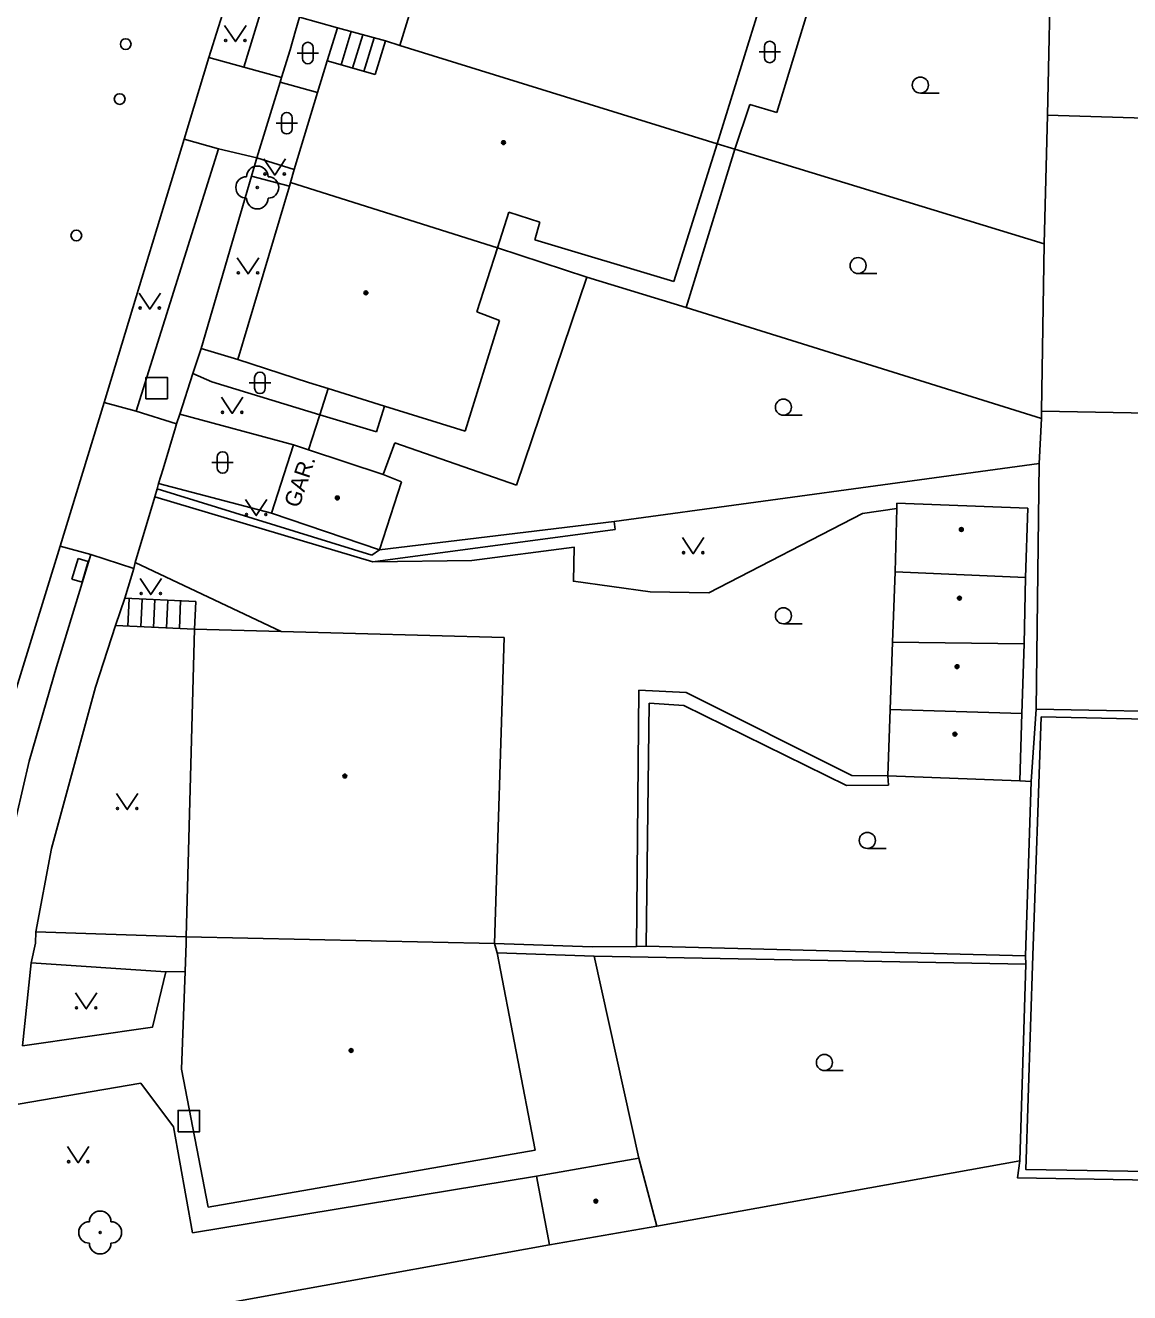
# Model space of a CAD drawing. Extents: x -600391 to -599491, y -1160176 to -1159402.
# Drawn here: x -599993.5 to -599942, y -1159653.5 to -1159594.4 of the extents above; entities that cross this region are included whole.
import ezdxf

# ---------------------------------------------------------------- set-up
doc = ezdxf.new("R2010")
doc.units = 0
for name, color, linetype in [('Level 10', 7, 'Continuous'), ('Level 11', 7, 'Continuous'), ('Level 22', 7, 'Continuous'), ('Level 26', 7, 'Continuous'), ('Level 28', 7, 'Continuous'), ('Level 36', 7, 'Continuous'), ('Level 39', 7, 'Continuous'), ('Level 41', 7, 'Continuous'), ('Level 5', 7, 'Continuous'), ('Level 51', 7, 'Continuous'), ('Level 52', 7, 'Continuous'), ('Level 6', 7, 'Continuous'), ('Level 7', 7, 'Continuous'), ('Level 8', 7, 'Continuous')]:
    doc.layers.add(name, color=color, linetype=linetype)

msp = doc.modelspace()

# ---------------------------------------------------------------- linework, layer by layer
at = {"layer": 'Level 10'}
for points in [[(-599984.03, -1159593.07), (-599984.92, -1159595.95)], [(-599984.92, -1159595.95), (-599986.07, -1159599.75)], [(-599986.07, -1159599.75), (-599988.15, -1159606.58), (-599989.8, -1159612.02)], [(-599989.8, -1159612.02), (-599991.85, -1159618.71)], [(-599991.85, -1159618.71), (-599998.93, -1159641.65)]]:
    msp.add_lwpolyline(points, dxfattribs=at)
at = {"layer": 'Level 11'}
for points in [[(-599982.43, -1159593.55), (-599983.3, -1159596.39)], [(-599979.42, -1159596.1), (-599978.93, -1159594.56)], [(-599978.77, -1159596.28), (-599978.29, -1159594.73)], [(-599978.24, -1159596.44), (-599977.75, -1159594.88)], [(-599977.71, -1159596.59), (-599977.22, -1159595.02)], [(-599983.3, -1159596.39), (-599984.92, -1159595.95)], [(-599983.3, -1159596.39), (-599981.54, -1159596.87)], [(-599982.69, -1159600.62), (-599981.61, -1159597.09)], [(-599986.07, -1159599.75), (-599984.47, -1159600.2)], [(-599984.47, -1159600.2), (-599988.31, -1159612.42)], [(-599984.47, -1159600.2), (-599982.69, -1159600.62)], [(-599982.69, -1159600.62), (-599982.94, -1159601.48)], [(-599980.95, -1159601.17), (-599982.69, -1159600.62)], [(-599983.58, -1159610.01), (-599985.29, -1159609.51)], [(-599985.68, -1159610.67), (-599984.79, -1159611.06), (-599979.75, -1159612.59)], [(-599979.75, -1159612.59), (-599979.37, -1159611.37)], [(-599988.31, -1159612.42), (-599989.8, -1159612.02)], [(-599976.75, -1159612.2), (-599977.11, -1159613.39)], [(-599988.31, -1159612.42), (-599986.43, -1159613.02)], [(-599980.98, -1159613.99), (-599986.28, -1159612.57)], [(-599980.29, -1159614.22), (-599979.77, -1159612.65)], [(-599979.77, -1159612.65), (-599979.75, -1159612.59)], [(-599979.75, -1159612.59), (-599977.11, -1159613.39)], [(-599982.01, -1159617.18), (-599987.27, -1159615.8)], [(-599991.85, -1159618.71), (-599990.42, -1159619.1)], [(-599990.42, -1159619.1), (-599992.02, -1159624.34), (-599993.3, -1159628.73), (-599994.19, -1159632.56), (-599994.89, -1159636.47), (-599995.74, -1159641.86)], [(-599991.31, -1159620.25), (-599991.02, -1159619.29)], [(-599991.02, -1159619.29), (-599990.55, -1159619.43)], [(-599990.55, -1159619.43), (-599990.83, -1159620.39)], [(-599990.42, -1159619.1), (-599988.42, -1159619.75)], [(-599988.36, -1159619.48), (-599981.56, -1159622.7)], [(-599990.83, -1159620.39), (-599991.31, -1159620.25)], [(-599988.84, -1159621.14), (-599985.54, -1159621.29)], [(-599988.7, -1159622.45), (-599988.64, -1159621.15)], [(-599988.1, -1159622.48), (-599988.04, -1159621.18)], [(-599987.44, -1159621.2), (-599987.5, -1159622.5)], [(-599986.9, -1159622.53), (-599986.84, -1159621.23)], [(-599986.24, -1159621.26), (-599986.3, -1159622.56)], [(-599985.6, -1159622.59), (-599985.54, -1159621.29)], [(-599985.6, -1159622.59), (-599989.28, -1159622.42)], [(-599993.2, -1159638.14), (-599986.93, -1159638.55)], [(-599986.93, -1159638.55), (-599987.55, -1159641.13), (-599993.61, -1159642)], [(-599986.93, -1159638.55), (-599986.03, -1159638.54)], [(-599988.1, -1159643.75), (-599993.81, -1159644.72)], [(-599986.58, -1159645.78), (-599988.1, -1159643.75)], [(-599985.69, -1159650.72), (-599986.58, -1159645.78)], [(-599969.66, -1159648.08), (-599985.69, -1159650.72)]]:
    msp.add_lwpolyline(points, dxfattribs=at)
at = {"layer": 'Level 22'}
for centre in [(-599982.67, -1159602), (-599989.99, -1159650.7)]:
    msp.add_circle(centre, 0.05, dxfattribs=at)
for centre, start, end in [((-599982.67, -1159601.5), 0, 180), ((-599983.17, -1159602), 90, 270), ((-599982.17, -1159602), 270, 90), ((-599982.67, -1159602.5), 180, 0), ((-599989.99, -1159650.2), 0, 180), ((-599990.49, -1159650.7), 90, 270), ((-599989.49, -1159650.7), 270, 90), ((-599989.99, -1159651.2), 180, 0)]:
    msp.add_arc(centre, 0.5, start, end, dxfattribs=at)
at = {"layer": 'Level 26'}
for points in [[(-599987.86, -1159611.85), (-599986.86, -1159611.85), (-599986.86, -1159610.85), (-599987.86, -1159610.85)], [(-599986.36, -1159646.01), (-599985.36, -1159646.01), (-599985.36, -1159645.01), (-599986.36, -1159645.01)]]:
    msp.add_lwpolyline(points, close=True, dxfattribs=at)
at = {"layer": 'Level 28'}
for centre in [(-599988.8, -1159595.32), (-599989.08, -1159597.88), (-599991.1, -1159604.24)]:
    msp.add_circle(centre, 0.25, dxfattribs=at)
at = {"layer": 'Level 36'}
for p, q in [((-599980.816, -1159595.736), (-599979.816, -1159595.736)), ((-599980.566, -1159595.486), (-599980.566, -1159595.986)), ((-599980.066, -1159595.486), (-599980.066, -1159595.986)), ((-599959.296, -1159595.686), (-599958.296, -1159595.686)), ((-599959.046, -1159595.436), (-599959.046, -1159595.936)), ((-599958.546, -1159595.436), (-599958.546, -1159595.936)), ((-599951.78, -1159597.605), (-599950.905, -1159597.605)), ((-599981.546, -1159598.756), (-599981.546, -1159599.256)), ((-599981.046, -1159598.756), (-599981.046, -1159599.256)), ((-599981.796, -1159599.006), (-599980.796, -1159599.006)), ((-599954.68, -1159606.015), (-599953.805, -1159606.015)), ((-599983.046, -1159611.106), (-599982.046, -1159611.106)), ((-599982.796, -1159610.856), (-599982.796, -1159611.356)), ((-599982.296, -1159610.856), (-599982.296, -1159611.356)), ((-599958.16, -1159612.615), (-599957.285, -1159612.615)), ((-599984.536, -1159614.566), (-599984.536, -1159615.066)), ((-599984.036, -1159614.566), (-599984.036, -1159615.066)), ((-599984.786, -1159614.816), (-599983.786, -1159614.816)), ((-599958.16, -1159622.335), (-599957.285, -1159622.335)), ((-599954.25, -1159632.805), (-599953.375, -1159632.805)), ((-599956.25, -1159643.155), (-599955.375, -1159643.155))]:
    msp.add_line(p, q, dxfattribs=at)
for points in [[(-599984.19, -1159594.45), (-599983.69, -1159595.2), (-599983.19, -1159594.45)], [(-599982.36, -1159600.67), (-599981.86, -1159601.42), (-599981.36, -1159600.67)], [(-599983.6, -1159605.28), (-599983.1, -1159606.03), (-599982.6, -1159605.28)], [(-599988.18, -1159606.92), (-599987.68, -1159607.67), (-599987.18, -1159606.92)], [(-599984.34, -1159611.78), (-599983.84, -1159612.53), (-599983.34, -1159611.78)], [(-599983.22, -1159616.54), (-599982.72, -1159617.29), (-599982.22, -1159616.54)], [(-599962.86, -1159618.32), (-599962.36, -1159619.07), (-599961.86, -1159618.32)], [(-599988.13, -1159620.22), (-599987.63, -1159620.97), (-599987.13, -1159620.22)], [(-599989.23, -1159630.24), (-599988.73, -1159630.99), (-599988.23, -1159630.24)], [(-599991.14, -1159639.53), (-599990.64, -1159640.28), (-599990.14, -1159639.53)], [(-599991.51, -1159646.7), (-599991.01, -1159647.45), (-599990.51, -1159646.7)]]:
    msp.add_lwpolyline(points, dxfattribs=at)
for centre, radius in [((-599984.14, -1159595.15), 0.05), ((-599983.241, -1159595.15), 0.05), ((-599951.78, -1159597.23), 0.375), ((-599982.31, -1159601.37), 0.05), ((-599981.411, -1159601.37), 0.05), ((-599954.68, -1159605.64), 0.375), ((-599983.55, -1159605.98), 0.05), ((-599982.651, -1159605.98), 0.05), ((-599988.13, -1159607.62), 0.05), ((-599987.231, -1159607.62), 0.05), ((-599958.16, -1159612.24), 0.375), ((-599984.29, -1159612.48), 0.05), ((-599983.391, -1159612.48), 0.05), ((-599983.17, -1159617.24), 0.05), ((-599982.271, -1159617.24), 0.05), ((-599962.81, -1159619.02), 0.05), ((-599961.911, -1159619.02), 0.05), ((-599988.08, -1159620.92), 0.05), ((-599987.181, -1159620.92), 0.05), ((-599958.16, -1159621.96), 0.375), ((-599989.18, -1159630.94), 0.05), ((-599988.281, -1159630.94), 0.05), ((-599954.25, -1159632.43), 0.375), ((-599991.09, -1159640.23), 0.05), ((-599990.191, -1159640.23), 0.05), ((-599956.25, -1159642.78), 0.375), ((-599991.46, -1159647.4), 0.05), ((-599990.561, -1159647.4), 0.05)]:
    msp.add_circle(centre, radius, dxfattribs=at)
for centre, start, end in [((-599980.316, -1159595.486), 0, 180), ((-599958.796, -1159595.436), 0, 180), ((-599980.316, -1159595.986), 180, 0), ((-599958.796, -1159595.936), 180, 0), ((-599981.296, -1159598.756), 0, 180), ((-599981.296, -1159599.256), 180, 0), ((-599982.546, -1159610.856), 0, 180), ((-599982.546, -1159611.356), 180, 0), ((-599984.286, -1159614.566), 0, 180), ((-599984.286, -1159615.066), 180, 0)]:
    msp.add_arc(centre, 0.25, start, end, dxfattribs=at)
at = {"layer": 'Level 39'}
for centre, radius in [((-599971.2, -1159599.91), 0.09), ((-599971.2, -1159599.91), 0.0398), ((-599977.61, -1159606.91), 0.09), ((-599977.61, -1159606.91), 0.0398), ((-599978.94, -1159616.47), 0.09), ((-599978.94, -1159616.47), 0.0398), ((-599949.87, -1159617.94), 0.09), ((-599949.87, -1159617.94), 0.0398), ((-599949.96, -1159621.14), 0.09), ((-599949.96, -1159621.14), 0.0398), ((-599950.07, -1159624.33), 0.09), ((-599950.07, -1159624.33), 0.0398), ((-599950.17, -1159627.48), 0.09), ((-599950.17, -1159627.48), 0.0398), ((-599978.59, -1159629.43), 0.09), ((-599978.59, -1159629.43), 0.0398), ((-599978.3, -1159642.22), 0.09), ((-599978.3, -1159642.22), 0.0398), ((-599966.9, -1159649.24), 0.09), ((-599966.9, -1159649.24), 0.0398)]:
    msp.add_circle(centre, radius, dxfattribs=at)
at = {"layer": 'Level 5'}
for points in [[(-599976.03, -1159595.38), (-599973.54, -1159587.29)], [(-599959.33, -1159593.82), (-599961.25, -1159599.97)], [(-599977.18, -1159596.74), (-599976.69, -1159595.17)], [(-599976.03, -1159595.38), (-599976.69, -1159595.17)], [(-599976.03, -1159595.38), (-599961.25, -1159599.97)], [(-599979.87, -1159597.58), (-599979.42, -1159596.1)], [(-599979.42, -1159596.1), (-599977.18, -1159596.74)], [(-599980.95, -1159601.17), (-599979.87, -1159597.58)], [(-599961.25, -1159599.97), (-599963.27, -1159606.39)], [(-599981.12, -1159601.77), (-599980.95, -1159601.17)], [(-599983.58, -1159610.01), (-599981.17, -1159601.94)], [(-599981.17, -1159601.94), (-599981.12, -1159601.77)], [(-599971.48, -1159604.82), (-599981.12, -1159601.77)], [(-599970.95, -1159603.15), (-599971.48, -1159604.82)], [(-599969.5, -1159603.61), (-599970.95, -1159603.15)], [(-599969.74, -1159604.44), (-599969.5, -1159603.61)], [(-599963.27, -1159606.39), (-599969.74, -1159604.44)], [(-599971.48, -1159604.82), (-599972.44, -1159607.8)], [(-599971.38, -1159608.2), (-599972.99, -1159613.35)], [(-599972.44, -1159607.8), (-599971.38, -1159608.2)], [(-599980.29, -1159611.09), (-599983.58, -1159610.01)], [(-599979.37, -1159611.37), (-599980.29, -1159611.09)], [(-599976.75, -1159612.2), (-599979.37, -1159611.37)], [(-599972.99, -1159613.35), (-599976.75, -1159612.2)], [(-599982.01, -1159617.18), (-599980.98, -1159613.99)], [(-599980.98, -1159613.99), (-599980.29, -1159614.22)], [(-599980.29, -1159614.22), (-599976.8, -1159615.37)], [(-599975.95, -1159615.72), (-599976.98, -1159618.89)], [(-599976.8, -1159615.37), (-599975.95, -1159615.72)], [(-599976.98, -1159618.89), (-599982.01, -1159617.18)], [(-599985.99, -1159636.92), (-599985.6, -1159622.59)], [(-599985.6, -1159622.59), (-599981.56, -1159622.7)], [(-599981.56, -1159622.7), (-599971.17, -1159622.98)], [(-599971.17, -1159622.98), (-599971.62, -1159637.24)], [(-599971.62, -1159637.24), (-599985.99, -1159636.92)], [(-599985.99, -1159637.22), (-599985.99, -1159636.92)], [(-599986.03, -1159638.54), (-599985.99, -1159637.22)], [(-599971.62, -1159637.24), (-599971.49, -1159637.67)], [(-599971.49, -1159637.67), (-599969.73, -1159646.86)], [(-599986.2, -1159643.09), (-599986.03, -1159638.54)], [(-599984.96, -1159649.52), (-599986.2, -1159643.09)], [(-599969.73, -1159646.86), (-599984.96, -1159649.52)], [(-599969.66, -1159648.08), (-599964.9, -1159647.23)], [(-599964.9, -1159647.23), (-599964.06, -1159650.4)], [(-599964.9, -1159647.23), (-599964.06, -1159650.4)], [(-599969.05, -1159651.28), (-599969.66, -1159648.08)], [(-599969.05, -1159651.28), (-599969.66, -1159648.08)], [(-599964.06, -1159650.4), (-599969.05, -1159651.28)], [(-599964.06, -1159650.4), (-599969.05, -1159651.28)]]:
    msp.add_lwpolyline(points, dxfattribs=at)
at = {"layer": 'Level 51'}
for points in [[(-599956.21, -1159591.11), (-599958.46, -1159598.51)], [(-599945.86, -1159598.63), (-599945.69, -1159590.69)], [(-599959.72, -1159598.14), (-599960.43, -1159600.22)], [(-599958.46, -1159598.51), (-599959.72, -1159598.14)], [(-599946.01, -1159604.63), (-599945.86, -1159598.63)], [(-599931.86, -1159599.07), (-599935.26, -1159598.96), (-599945.86, -1159598.63)], [(-599961.25, -1159599.97), (-599960.43, -1159600.22)], [(-599960.43, -1159600.22), (-599962.69, -1159607.59)], [(-599960.43, -1159600.22), (-599946.01, -1159604.63)], [(-599946.13, -1159612.42), (-599946.01, -1159604.63)], [(-599971.48, -1159604.82), (-599967.32, -1159606.18)], [(-599967.32, -1159606.18), (-599970.6, -1159615.88)], [(-599967.32, -1159606.18), (-599962.69, -1159607.59)], [(-599962.69, -1159607.59), (-599946.13, -1159612.76)], [(-599946.25, -1159614.86), (-599946.13, -1159612.76)], [(-599919.38, -1159612.92), (-599946.13, -1159612.42)], [(-599946.13, -1159612.42), (-599946.13, -1159612.76)], [(-599976.27, -1159613.9), (-599976.8, -1159615.37)], [(-599970.6, -1159615.88), (-599976.27, -1159613.9)], [(-599946.25, -1159614.86), (-599966.04, -1159617.56)], [(-599946.38, -1159626.32), (-599946.25, -1159614.86)], [(-599977.28, -1159619.44), (-599972.67, -1159619.38), (-599967.9, -1159618.77), (-599967.94, -1159620.35), (-599964.37, -1159620.84), (-599961.64, -1159620.89), (-599954.47, -1159617.19), (-599952.88, -1159616.96)], [(-599966.04, -1159617.56), (-599976.98, -1159618.89)], [(-599965.99, -1159617.94), (-599966.04, -1159617.56)], [(-599977.28, -1159619.44), (-599965.99, -1159617.94)], [(-599964.89, -1159625.43), (-599965.01, -1159637.37)], [(-599962.69, -1159625.53), (-599964.89, -1159625.43)], [(-599954.97, -1159629.41), (-599962.69, -1159625.53)], [(-599964.41, -1159626.04), (-599964.56, -1159637.36)], [(-599962.8, -1159626.14), (-599964.41, -1159626.04)], [(-599955.22, -1159629.87), (-599962.8, -1159626.14)], [(-599946.62, -1159629.69), (-599946.38, -1159626.32)], [(-599930.01, -1159626.62), (-599946.38, -1159626.32)], [(-599946.54, -1159637.8), (-599946.15, -1159626.67)], [(-599946.15, -1159626.67), (-599930.02, -1159627.03)], [(-599953.29, -1159629.42), (-599954.97, -1159629.41)], [(-599953.29, -1159629.42), (-599953.27, -1159629.86)], [(-599953.27, -1159629.86), (-599955.22, -1159629.87)], [(-599946.62, -1159629.69), (-599947.15, -1159629.66)], [(-599946.88, -1159637.81), (-599946.62, -1159629.69)], [(-599971.62, -1159637.24), (-599967.07, -1159637.39)], [(-599971.49, -1159637.67), (-599966.98, -1159637.82)], [(-599967.07, -1159637.39), (-599965.01, -1159637.37)], [(-599965.01, -1159637.37), (-599964.56, -1159637.36)], [(-599964.56, -1159637.36), (-599946.88, -1159637.81)], [(-599966.98, -1159637.82), (-599964.9, -1159647.23)], [(-599966.98, -1159637.82), (-599946.87, -1159638.19)]]:
    msp.add_lwpolyline(points, dxfattribs=at)
at = {"layer": 'Level 52'}
for points in [[(-599952.95, -1159619.91), (-599952.88, -1159616.96)], [(-599952.88, -1159616.96), (-599952.87, -1159616.72)], [(-599952.87, -1159616.72), (-599946.77, -1159616.94)], [(-599946.77, -1159616.94), (-599946.88, -1159620.18)], [(-599953.08, -1159623.19), (-599952.95, -1159619.91)], [(-599946.88, -1159620.18), (-599952.95, -1159619.91)], [(-599946.88, -1159620.18), (-599946.94, -1159623.27)], [(-599953.19, -1159626.33), (-599953.08, -1159623.19)], [(-599946.94, -1159623.27), (-599953.08, -1159623.19)], [(-599946.94, -1159623.27), (-599947.05, -1159626.52)], [(-599953.29, -1159629.42), (-599953.19, -1159626.33)], [(-599947.05, -1159626.52), (-599953.19, -1159626.33)], [(-599947.05, -1159626.52), (-599947.15, -1159629.66)], [(-599947.15, -1159629.66), (-599953.29, -1159629.42)]]:
    msp.add_lwpolyline(points, dxfattribs=at)
at = {"layer": 'Level 6'}
msp.add_lwpolyline([(-599979.87, -1159597.58), (-599980.95, -1159601.17)], dxfattribs=at)
at = {"layer": 'Level 7'}
for points in [[(-599980.7, -1159594.07), (-599980.89, -1159594.7)], [(-599978.93, -1159594.56), (-599980.7, -1159594.07)], [(-599976.69, -1159595.17), (-599978.93, -1159594.56)], [(-599981.14, -1159595.59), (-599981.54, -1159596.87)], [(-599981.54, -1159596.87), (-599981.61, -1159597.09)], [(-599979.87, -1159597.58), (-599981.61, -1159597.09)], [(-599985.29, -1159609.51), (-599982.94, -1159601.48)], [(-599982.94, -1159601.48), (-599981.17, -1159601.94)], [(-599986.28, -1159612.57), (-599985.68, -1159610.67)], [(-599986.43, -1159613.02), (-599986.28, -1159612.57)], [(-599986.48, -1159613.19), (-599986.43, -1159613.02)], [(-599987.27, -1159615.8), (-599987.06, -1159615.12)], [(-599987.34, -1159616.04), (-599987.27, -1159615.8)], [(-599987.34, -1159616.04), (-599987.45, -1159616.42)], [(-599987.45, -1159616.42), (-599977.28, -1159619.44)], [(-599977.34, -1159619.14), (-599987.34, -1159616.04)], [(-599977.34, -1159619.14), (-599976.98, -1159618.89)], [(-599988.84, -1159621.14), (-599988.42, -1159619.75)], [(-599988.42, -1159619.75), (-599988.36, -1159619.48)], [(-599992.98, -1159636.69), (-599992.25, -1159632.81), (-599990.21, -1159625.28), (-599989.28, -1159622.42)], [(-599993, -1159637.22), (-599992.98, -1159636.69)], [(-599992.98, -1159636.69), (-599985.99, -1159636.92)], [(-599993.61, -1159642), (-599993.2, -1159638.14)], [(-599947.14, -1159647.36), (-599946.87, -1159638.19)], [(-599947.14, -1159647.36), (-599946.87, -1159638.19)], [(-599946.87, -1159638.19), (-599946.88, -1159637.81)], [(-599924.03, -1159648.14), (-599946.87, -1159647.76), (-599946.54, -1159637.8)], [(-599947.14, -1159647.36), (-599964.06, -1159650.4)], [(-599947.14, -1159647.36), (-599964.06, -1159650.4)], [(-599924.07, -1159648.56), (-599930.29, -1159648.45), (-599947.25, -1159648.16), (-599947.14, -1159647.36)], [(-599924.07, -1159648.56), (-599930.29, -1159648.45), (-599947.25, -1159648.16), (-599947.14, -1159647.36)], [(-599969.05, -1159651.28), (-599981.615, -1159653.545), (-599983.92, -1159653.96), (-599993.47, -1159655.78)], [(-599969.05, -1159651.28), (-599981.615, -1159653.545), (-599983.92, -1159653.96), (-599993.47, -1159655.78)]]:
    msp.add_lwpolyline(points, dxfattribs=at)
at = {"layer": 'Level 8'}
for points in [[(-599980.89, -1159594.7), (-599981.14, -1159595.59)], [(-599985.29, -1159609.51), (-599985.68, -1159610.67)], [(-599986.48, -1159613.19), (-599987.06, -1159615.12)], [(-599987.45, -1159616.42), (-599988.36, -1159619.48)], [(-599988.84, -1159621.14), (-599989.28, -1159622.42)], [(-599993, -1159637.22), (-599993.2, -1159638.14)]]:
    msp.add_lwpolyline(points, dxfattribs=at)

# ---------------------------------------------------------------- texts
at = {"layer": 'Level 41'}
msp.add_text('GAR.', height=0.75, rotation=71.38, dxfattribs=at).set_placement((-599980.73, -1159616.97))

doc.saveas('drawing.dxf')
